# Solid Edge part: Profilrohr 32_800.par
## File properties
Username: ahadarics
Dokumentum tartalom típus: 0
Author: ahadarics
Last saved by: ahadarics
Revision: 97
Sűrűség: 0,000 kg/m^3
Pontosság: 0,990
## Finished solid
Body 1: solid body, 179 faces, 531 edges, 354 vertices.
  Faces by surface: cylinder 109, plane 70
  Edges by curve: line 313, circle 218
Bounding box of the edges (mm): 44.254 x 841.000 x 44.254, from (-22.1268, -808, -22.1268) to (22.1268, 33, 22.1268).
Cylindrical faces by radius (mm): R0.1 x16, R0.2 x30, R0.5 x32, R1 x6, R2.7 x8, R4.5 x4, R4.7 x4, R16 x1, R18 x8
Planar faces by outward normal: +x 4, +y 1, +z 6, -x 6, -y 1, -z 4, oblique 48
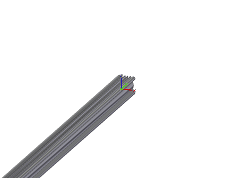
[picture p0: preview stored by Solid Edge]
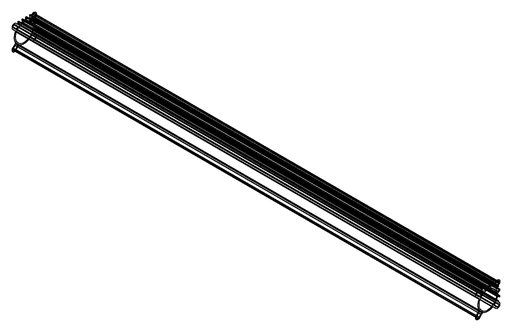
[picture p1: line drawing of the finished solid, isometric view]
